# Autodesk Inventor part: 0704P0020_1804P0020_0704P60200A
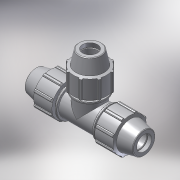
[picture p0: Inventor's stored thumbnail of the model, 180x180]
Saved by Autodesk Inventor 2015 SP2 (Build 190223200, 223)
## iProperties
Created: 2017-02
Part Number: 0704P0020_1804P0020_0704P60200A
Material: PVC-Piping
Description: PLASSON REPAIR TEE 20
Document SubType Name: Modeling
Designer: KIM
Mass: 92.6774 g
Surface Area: 199.44 cm^2
Volume: 66.1981 cm^3
Density: 1.4 g/cm^3
Appearance: Smooth - White
Author: Кирилл
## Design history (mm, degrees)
derived "0704P0.ipt"
feature "Solid1::0704P0.ipt"
tag "TaggingFeature1"
body "Solid1"
other parameters: "d4" = 6.08333, "d5" = 18.25, "d7" = 48, "d11" = 2.43333, "d13" = 120 deg, "d15" = 12 deg, "d16" = 41.76, "d18" = 1, "d19" = 35 deg, "d20" = 17.5 deg, "d21" = 44.64, "d23" = 0, "d25" = 360 deg, "d27" = 0.96, "d33" = 0.4, "d42" = 25.55, "d43" = 1.44, "d46" = 0.6, "d63" = 56, "d67" = 36, "d77" = 48, "d78" = 12 deg, "d79" = 73, "d80" = 120 deg, "d82" = 6.08333, "d85" = 36, "d86" = 41.76, "d87" = 2.43333, "d88" = 2.43333, "d89" = 18.25, "d90" = 25.55, "d96" = 7.3, "d98" = 44.64, "d99" = 35 deg, "d100" = 17.5 deg, "d102" = 0, "d103" = 0.96, "d107" = 360 deg, "d109" = 0.6, "d112" = 1, "d118" = 360 deg, "d121" = 0, "d128" = 145, "d131" = 18, "d132" = 18, "d133" = 56, "d134" = 1.12, "d135" = 7.3, "d152" = 0, "d154" = 0, "d156" = 0, "d158" = 0, "E_" = 48, "A_" = 73, "l_" = 56, "H_" = 145
